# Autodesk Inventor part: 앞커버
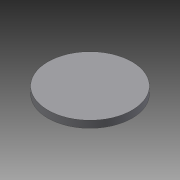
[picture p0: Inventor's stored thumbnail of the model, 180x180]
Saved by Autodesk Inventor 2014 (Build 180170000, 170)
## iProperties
Created: 2024-02
Part Number: 앞커버
Material: 알루미늄 6061
Document SubType Name: Modeling
Designer: mdu-01
Density: 2.71 g/cm^3
Mass: 306.092 g
Surface Area: 299.031 cm^2
Volume: 112.949 cm^3
Appearance: 기본값(1)
Author: mdu-01
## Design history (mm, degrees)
sketch "스케치1"
  geometry: C1 r 60 at (0, 0) reference; C2 r 46 at (0, 0) reference; C3 r 15 at (0, 0) reference; C4 r 11 at (0, -31) reference; A1 r 41 centre (0, 0) between (20.39, -35.57) and (-20.39, -35.57); A2 r 20 centre (0, 0) between (12.218, -15.835) and (-12.218, -15.835); A3 r 16 centre (0, -31) between (-11.832, -20.229) and (-15.914, -32.657); A4 r 16 centre (0, -31) between (15.914, -32.657) and (11.832, -20.229); A5 r 3 centre (-14.05, -18.21) between (-11.832, -20.229) and (-12.218, -15.835); A6 r 3 centre (14.05, -18.21) between (12.218, -15.835) and (11.832, -20.229); A7 r 3 centre (18.898, -32.968) between (15.914, -32.657) and (20.39, -35.57); A8 r 3 centre (-18.898, -32.968) between (-20.39, -35.57) and (-15.914, -32.657); 1 further point
  constraints: 16 point on circle, 8 centre point, 8 tangent, 4 equal radius
  dimensions: "d0" = 5 radial gap between concentric circles of C2 A1; "d1" = 5 radial gap between concentric circles of A2 C3; "d3" = 5 radial gap between concentric circles of A4 C4; "d4" = 3 radius of A5
  node "참조1"
  node "참조2"
  node "참조3"
  node "참조4"
extrude "돌출1" new body sketch "스케치1" distance "d5" = 10; taper "d6" = 0 deg
extrude "돌출2" join sketch "스케치1" distance "d7" = 3; taper "d8" = 0 deg
sketch "스케치2"
  geometry: C1 r 20 at (0, 0); 1 further point
  constraints: 1 centre point, 1 coincident
  dimensions: "d9" = 40 diameter of C1
extrude "돌출3" join sketch "스케치2" distance "d10" = 7; taper "d11" = 0 deg
fillet "모깎기1" dims "d12" = 3
chamfer "모따기1" distance "d13" = 1; stored, may be unused: second distance "d14" = 2, angle "d15" = 45 deg
sketch "스케치3"
  geometry: C1 r 1.621 at (0, 52) reference; 1 further point
hole "구멍1" sketch "스케치3" at (0, 52) diameter "d16" = 4.5; stored, may be unused: countersink angle "d20" = 90 deg, drill point angle "d22" = 118 deg; dims "d17" = 6, "d18" = 8, "d19" = 4.4, "d21" = 8
sketch "스케치4"
  geometry: L1 (15, 3.7)-(15, -2.7) reference; L2 (-14.7, 4)-(14.7, 4) reference; L3 (14.7, -3)-(-14.7, -3) reference; L4 (14.7, 4)-(13, 4); L5 (-17, 17)-(17, 17) reference; L6 (15, 16.2)-(15, 9); L7 (14.7, 8.7)-(13, 8.7); L8 (13, 8.7)-(13, 4); L9 (0, 17)-(0, -3); L10 (15.462, 17)-(15, 16.2); L11 (14.7, -3)-(15, -3); L12 (15, -3)-(15, -2.7); A1 r 0.3 centre (14.7, 3.7) between (15, 3.7) and (14.7, 4); A2 r 0.3 centre (14.7, 9) between (14.7, 8.7) and (15, 9); 1 further point
  constraints: 18 end point, 4 point on circle, 3 perpendicular, 3 tangent, 2 centre point, 2 midpoint, 2 point on line, 1 collinear, 1 parallel, 1 vertical, 2 other
  dimensions: "d26" = 2 distance from line of L4.end L1; "d28" = 0.3 radius of A2; "d29" = 30 diameter of L6 L9; "d30" = 8.3 distance between parallel lines of L7 L5; "d31" = 0.8 distance from line of L6.start L5; "d32" = 30 deg angle of L6 L10
revolve "회전1" sketch "스케치4" stored, may be unused: angle "d33" = 90 deg
sketch "스케치5"
  geometry: L1 (-20, 3.7)-(-20, -2.7) reference; L2 (-20.3, -3)-(-41.7, -3) reference; L3 (-41.7, 4)-(-20.3, 4) reference; L4 (-20.3, 4)-(-22, 4); L5 (-20, -2.7)-(-20, -3); L6 (-20, -3)-(-20.3, -3); L7 (-31, -3)-(-31, 7); L8 (-31, 7)-(-25, 7); A1 r 0.3 centre (-20.3, 3.7) between (-20, 3.7) and (-20.3, 4); A2 r 3 centre (-25, 4) between (-22, 4) and (-25, 7); 1 further point
  constraints: 12 end point, 4 perpendicular, 4 point on circle, 2 centre point, 2 point on line, 2 tangent, 1 midpoint, 1 vertical, 2 other
  dimensions: "d34" = 3 distance between parallel lines of L8 L3; "d35" = 2 distance from line of L4.end L1
revolve "회전2" sketch "스케치5" stored, may be unused: angle "d36" = 90 deg
chamfer "모따기2" distance "d37" = 1; stored, may be unused: second distance "d38" = 2, angle "d39" = 45 deg
node "솔리드1"
pattern_circular "원형 패턴1" dims angle "d24" = 360 deg
node "참조5"
node "참조6"
node "참조7"
node "참조8"
node "참조9"
other parameters: "d2" = 5
